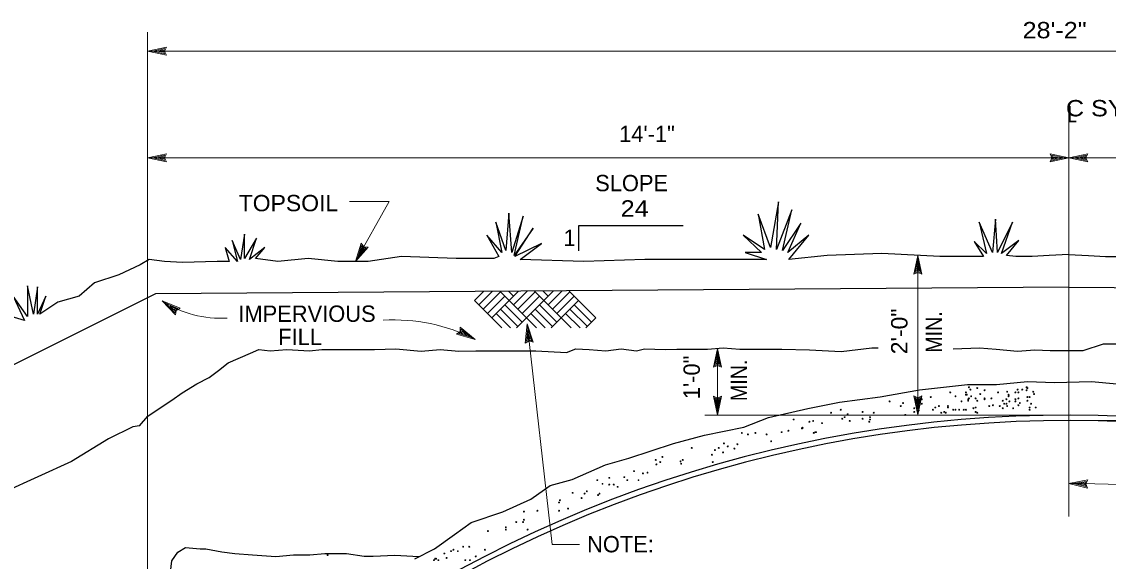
# Model space of a CAD drawing. Extents: x -24.3 to 17.7, y -17.6 to 12.4.
# Drawn here: x -17.91 to -9.61, y -5.14 to -1.01 of the extents above; entities that cross this region are included whole.
import ezdxf
from ezdxf.enums import TextEntityAlignment as Align

# ---------------------------------------------------------------- set-up
doc = ezdxf.new("R2010")
doc.units = 0
doc.header["$LTSCALE"] = 0.05
doc.layers.add('1', color=7, linetype='Continuous', lineweight=13)

msp = doc.modelspace()

# ---------------------------------------------------------------- linework, layer by layer
at = {"layer": '1'}
for p, q in [((-16.95069, -7.6306), (-16.95069, -1.0886)), ((-16.95069, -1.2326), (-16.80669, -1.2016)), ((-16.95069, -1.2326), (-2.86269, -1.2326)), ((-16.95069, -1.2326), (-16.80669, -1.2636)), ((-16.91369, -1.2326), (-16.81969, -1.2126)), ((-16.91369, -1.2326), (-16.81969, -1.2526)), ((-16.87769, -1.2326), (-16.83269, -1.2226)), ((-16.87769, -1.2326), (-16.83269, -1.2416)), ((-16.83269, -1.2226), (-16.83669, -1.2326)), ((-16.83669, -1.2326), (-16.83269, -1.2416)), ((-16.81969, -1.2126), (-16.82869, -1.2326)), ((-16.82869, -1.2326), (-16.81969, -1.2526)), ((-9.90869, -4.7916), (-9.90869, -1.6566)), ((-16.95069, -2.0496), (-16.80669, -2.0186)), ((-16.95069, -2.0496), (-16.80669, -2.0806)), ((-16.91369, -2.0496), (-16.81969, -2.0296)), ((-16.91369, -2.0496), (-16.81969, -2.0696)), ((-16.87769, -2.0496), (-16.83269, -2.0396)), ((-16.87769, -2.0496), (-16.83269, -2.0586)), ((-16.83269, -2.0396), (-16.83669, -2.0496)), ((-16.83669, -2.0496), (-16.83269, -2.0586)), ((-16.81969, -2.0296), (-16.82869, -2.0496)), ((-16.82869, -2.0496), (-16.81969, -2.0696)), ((-9.90769, -2.0496), (-10.05169, -2.0186)), ((-9.90769, -2.0496), (-10.05169, -2.0806)), ((-9.94469, -2.0496), (-10.03869, -2.0296)), ((-10.02969, -2.0496), (-10.03869, -2.0296)), ((-9.94469, -2.0496), (-10.03869, -2.0696)), ((-10.03869, -2.0696), (-10.02969, -2.0496)), ((-9.98069, -2.0496), (-10.02569, -2.0406)), ((-10.02169, -2.0496), (-10.02569, -2.0406)), ((-9.98069, -2.0496), (-10.02569, -2.0596)), ((-10.02569, -2.0596), (-10.02169, -2.0496)), ((-9.90769, -2.0496), (-9.76369, -2.0186)), ((-9.90769, -2.0496), (-9.76369, -2.0806)), ((-9.87069, -2.0496), (-9.77669, -2.0296)), ((-9.87069, -2.0496), (-9.77669, -2.0696)), ((-9.83469, -2.0496), (-9.78969, -2.0396)), ((-9.83469, -2.0496), (-9.78969, -2.0586)), ((-9.78969, -2.0396), (-9.79369, -2.0496)), ((-9.79369, -2.0496), (-9.78969, -2.0586)), ((-9.77669, -2.0296), (-9.78569, -2.0496)), ((-9.78569, -2.0496), (-9.77669, -2.0696)), ((-15.36169, -2.8426), (-15.26369, -2.7326)), ((-15.34369, -2.8106), (-15.31469, -2.7186)), ((-15.34369, -2.8106), (-15.27969, -2.7386)), ((-15.32569, -2.7786), (-15.31269, -2.7346)), ((-15.31469, -2.7186), (-15.30169, -2.7366)), ((-15.31269, -2.7346), (-15.30569, -2.7436)), ((-15.30169, -2.7366), (-15.27969, -2.7386)), ((-15.32569, -2.7786), (-15.29569, -2.7446)), ((-15.30569, -2.7436), (-15.29569, -2.7446)), ((-11.06169, -2.7956), (-11.09269, -2.9396)), ((-11.06169, -4.0166), (-11.06169, -2.7956)), ((-11.06169, -2.7956), (-11.03069, -2.9396)), ((-11.06169, -2.8326), (-11.08169, -2.9266)), ((-11.06169, -2.8686), (-11.07069, -2.9136)), ((-11.06169, -2.8326), (-11.04169, -2.9266)), ((-11.06169, -2.8686), (-11.05169, -2.9136)), ((-11.06169, -2.9176), (-11.08169, -2.9266)), ((-11.06169, -2.9096), (-11.07069, -2.9136)), ((-11.05169, -2.9136), (-11.06169, -2.9096)), ((-11.04169, -2.9266), (-11.06169, -2.9176)), ((-14.45069, -3.1406), (-14.37969, -3.0696)), ((-14.41769, -3.1736), (-14.31369, -3.0696)), ((-14.18569, -3.1406), (-14.25669, -3.0696)), ((-14.15269, -3.1076), (-14.19069, -3.0696)), ((-14.18569, -3.1406), (-14.11469, -3.0696)), ((-14.18569, -3.1406), (-14.11469, -3.0696)), ((-14.15269, -3.1736), (-14.04869, -3.0696)), ((-14.11969, -3.0746), (-14.12469, -3.0696)), ((-13.92069, -3.1406), (-13.99169, -3.0696)), ((-13.88769, -3.1076), (-13.92569, -3.0696)), ((-13.92069, -3.1406), (-13.84969, -3.0696)), ((-13.88769, -3.1736), (-13.78269, -3.0696)), ((-13.85469, -3.0746), (-13.85869, -3.0696)), ((-13.65569, -3.1406), (-13.72669, -3.0696)), ((-16.83769, -3.1426), (-16.70169, -3.1996)), ((-16.83769, -3.1426), (-16.73769, -3.2506)), ((-14.38469, -3.2066), (-14.25169, -3.0746)), ((-14.35169, -3.2406), (-14.21869, -3.1076)), ((-14.31869, -3.2736), (-14.18569, -3.1406)), ((-14.05269, -3.2736), (-14.18569, -3.1406)), ((-14.11969, -3.2066), (-13.98669, -3.0746)), ((-14.08669, -3.2406), (-13.95369, -3.1076)), ((-14.05269, -3.2736), (-13.92069, -3.1406)), ((-13.85469, -3.2066), (-13.72169, -3.0746)), ((-13.82069, -3.2406), (-13.68869, -3.1076)), ((-13.78769, -3.2736), (-13.65569, -3.1406)), ((-13.52269, -3.2736), (-13.65569, -3.1406)), ((-16.80769, -3.1636), (-16.71869, -3.2016)), ((-16.80769, -3.1636), (-16.74169, -3.2346)), ((-16.77769, -3.1846), (-16.74569, -3.2176)), ((-16.77769, -3.1846), (-16.73569, -3.2016)), ((-16.74469, -3.2076), (-16.74569, -3.2176)), ((-16.73569, -3.2016), (-16.74469, -3.2076)), ((-16.73769, -3.2126), (-16.74169, -3.2346)), ((-16.71869, -3.2016), (-16.73769, -3.2126)), ((-14.11969, -3.3396), (-14.25169, -3.2066)), ((-14.08669, -3.3066), (-14.21869, -3.1736)), ((-13.85469, -3.3396), (-13.98669, -3.2066)), ((-13.82069, -3.3066), (-13.95369, -3.1736)), ((-13.58869, -3.3396), (-13.72169, -3.2066)), ((-13.55569, -3.3066), (-13.68869, -3.1736)), ((-14.17569, -3.3496), (-14.28569, -3.2406)), ((-14.12969, -3.3496), (-14.05269, -3.2736)), ((-14.04869, -3.3196), (-14.06369, -3.4666)), ((-13.97669, -3.3496), (-14.05269, -3.2736)), ((-13.91069, -3.3496), (-14.01969, -3.2406)), ((-13.86469, -3.3496), (-13.78769, -3.2736)), ((-13.64469, -3.3496), (-13.75469, -3.2406)), ((-13.59969, -3.3496), (-13.52269, -3.2736)), ((-14.44669, -3.4376), (-14.58869, -3.3976)), ((-14.57169, -3.3946), (-14.55469, -3.3806)), ((-14.47969, -3.4206), (-14.57169, -3.3946)), ((-14.44669, -3.4376), (-14.55969, -3.3436)), ((-14.55569, -3.3916), (-14.54769, -3.3846)), ((-14.51169, -3.4036), (-14.55569, -3.3916)), ((-14.55469, -3.3806), (-14.55369, -3.3586)), ((-14.47969, -3.4206), (-14.55369, -3.3586)), ((-14.54769, -3.3846), (-14.54669, -3.3746)), ((-14.51169, -3.4036), (-14.54669, -3.3746)), ((-14.04469, -3.3566), (-14.05369, -3.4516)), ((-14.04469, -3.3566), (-14.01369, -3.4476)), ((-14.04069, -3.3926), (-14.04469, -3.4376)), ((-14.04069, -3.3926), (-14.02569, -3.4356)), ((-14.03469, -3.4406), (-14.05369, -3.4516)), ((-14.03569, -3.4326), (-14.04469, -3.4376)), ((-14.02569, -3.4356), (-14.03569, -3.4326)), ((-14.01369, -3.4476), (-14.03469, -3.4406)), ((-12.59369, -3.5066), (-12.62469, -3.6506)), ((-12.59369, -3.5436), (-12.61369, -3.6376)), ((-12.59369, -4.0166), (-12.59369, -3.5066)), ((-12.59369, -3.5066), (-12.56269, -3.6506)), ((-12.59369, -3.5436), (-12.57369, -3.6376)), ((-12.59369, -3.6286), (-12.61369, -3.6376)), ((-12.59369, -3.5796), (-12.60269, -3.6246)), ((-12.59369, -3.6206), (-12.60269, -3.6246)), ((-12.59369, -3.5796), (-12.58369, -3.6246)), ((-12.58369, -3.6246), (-12.59369, -3.6206)), ((-12.57369, -3.6376), (-12.59369, -3.6286)), ((-12.59369, -4.0166), (-12.62469, -3.8726)), ((-12.59369, -3.9796), (-12.61369, -3.8856)), ((-12.61369, -3.8856), (-12.59369, -3.8946)), ((-12.59369, -3.9436), (-12.60369, -3.8986)), ((-12.60369, -3.8986), (-12.59369, -3.9026)), ((-12.59369, -4.0166), (-12.56269, -3.8726)), ((-12.59369, -3.9796), (-12.57369, -3.8856)), ((-12.59369, -3.8946), (-12.57369, -3.8856)), ((-12.59369, -3.9436), (-12.58469, -3.8986)), ((-12.59369, -3.9026), (-12.58469, -3.8986)), ((-11.06169, -4.0136), (-11.09269, -3.8696)), ((-11.06169, -3.9766), (-11.08169, -3.8826)), ((-11.08169, -3.8826), (-11.06169, -3.8916)), ((-11.06169, -3.9406), (-11.07169, -3.8956)), ((-11.07169, -3.8956), (-11.06169, -3.8996)), ((-11.06169, -4.0136), (-11.03069, -3.8696)), ((-11.06169, -3.9766), (-11.04169, -3.8826)), ((-11.06169, -3.8916), (-11.04169, -3.8826)), ((-11.06169, -3.9406), (-11.05269, -3.8956)), ((-11.06169, -3.8996), (-11.05269, -3.8956)), ((-9.90269, -4.0166), (-12.69069, -4.0166)), ((-9.89169, -4.0586), (-9.94069, -4.0586)), ((-9.90969, -4.0576), (-0.82769, -4.0576)), ((-9.90869, -4.5396), (-9.76369, -4.5126)), ((-9.90869, -4.5396), (-9.76569, -4.5746)), ((-9.87169, -4.5406), (-9.77669, -4.5236)), ((-9.87169, -4.5406), (-9.77869, -4.5636)), ((-9.83569, -4.5416), (-9.79069, -4.5336)), ((-9.83569, -4.5416), (-9.79069, -4.5526)), ((-9.79069, -4.5336), (-9.79469, -4.5436)), ((-9.79469, -4.5436), (-9.79069, -4.5526)), ((-9.77669, -4.5236), (-9.78669, -4.5436)), ((-9.78669, -4.5436), (-9.77869, -4.5636)), ((-13.85769, -5.0076), (-13.64969, -5.0076))]:
    msp.add_line(p, q, dxfattribs=at)
at = {"layer": '1', "lineweight": 25}
for p, q in [((-9.90769, -3.0386), (-16.88969, -3.0886)), ((-16.88969, -3.0886), (-20.42169, -4.8536)), ((-17.01169, -4.0986), (-17.06169, -4.1056))]:
    msp.add_line(p, q, dxfattribs=at)
at = {"layer": '1'}
for points in [[(-16.80669, -1.2016), (-16.82069, -1.2326), (-16.80669, -1.2636)], [(-16.95069, -2.0496), (-9.90769, -2.0496), (-2.86269, -2.0496)], [(-16.80669, -2.0186), (-16.82069, -2.0496), (-16.80669, -2.0806)], [(-10.05169, -2.0806), (-10.03769, -2.0496), (-10.05169, -2.0186)], [(-9.76369, -2.0186), (-9.77769, -2.0496), (-9.76369, -2.0806)], [(-15.40669, -2.3826), (-15.10269, -2.3826), (-15.36169, -2.8426), (-15.31769, -2.7016)], [(-15.31769, -2.7016), (-15.29769, -2.7296), (-15.26369, -2.7326)], [(-11.03069, -2.9396), (-11.06169, -2.9256), (-11.09269, -2.9396)], [(-13.71169, -3.3496), (-13.92069, -3.1406), (-13.84969, -3.0696)], [(-14.24169, -3.3496), (-14.31869, -3.2736), (-14.45069, -3.1406)], [(-16.70169, -3.1996), (-16.73069, -3.2176), (-16.73769, -3.2506)], [(-13.85769, -5.0076), (-14.04869, -3.3196), (-14.00169, -3.4596)], [(-14.58869, -3.3976), (-14.56169, -3.3766), (-14.55969, -3.3436)], [(-14.00169, -3.4596), (-14.03369, -3.4486), (-14.06369, -3.4666)], [(-12.56269, -3.6506), (-12.59369, -3.6366), (-12.62469, -3.6506)], [(-12.62469, -3.8726), (-12.59369, -3.8866), (-12.56269, -3.8726)], [(-11.09269, -3.8696), (-11.06169, -3.8836), (-11.03069, -3.8696)], [(-9.76369, -4.5126), (-9.77869, -4.5436), (-9.76569, -4.5746)]]:
    msp.add_lwpolyline(points, dxfattribs=at)
at = {"layer": '1', "lineweight": 25}
for points in [[(-9.90769, -2.7886), (-10.05869, -2.7966), (-10.18969, -2.8046), (-10.31369, -2.8046), (-10.38369, -2.7966), (-10.29069, -2.6806), (-10.42269, -2.7816), (-10.33769, -2.5406), (-10.45369, -2.7736), (-10.46869, -2.5176), (-10.49269, -2.7736), (-10.59269, -2.5406), (-10.53869, -2.7816), (-10.63169, -2.6886), (-10.56169, -2.8046), (-10.89469, -2.8046), (-11.33669, -2.7816), (-11.75469, -2.7966), (-12.04969, -2.8276), (-11.89469, -2.6416), (-12.05669, -2.7736), (-11.95669, -2.5486), (-12.09569, -2.7576), (-12.02669, -2.4476), (-12.14269, -2.7506), (-12.12669, -2.3856), (-12.18869, -2.7346), (-12.28169, -2.4786), (-12.23569, -2.7506), (-12.39769, -2.6416), (-12.25869, -2.7736), (-12.38269, -2.7736), (-12.21969, -2.8276), (-12.79269, -2.8276), (-13.14969, -2.8276), (-13.61469, -2.8426), (-14.10269, -2.8276), (-13.93969, -2.7036), (-14.14169, -2.8046), (-14.00169, -2.5876), (-14.14869, -2.7966), (-14.07969, -2.4946), (-14.16469, -2.7736), (-14.18769, -2.4716), (-14.21069, -2.7576), (-14.28869, -2.5406), (-14.24169, -2.7736), (-14.35769, -2.6416), (-14.26569, -2.8046), (-14.30369, -2.8196), (-14.59069, -2.8196), (-15.00869, -2.8046), (-15.26469, -2.8426), (-15.49669, -2.8426), (-15.72169, -2.8196), (-15.95369, -2.8426), (-16.12469, -2.8196), (-16.05469, -2.7346), (-16.17069, -2.8276), (-16.11669, -2.6646), (-16.20969, -2.8196), (-16.20969, -2.6336), (-16.24069, -2.8276), (-16.30269, -2.6806), (-16.26369, -2.8426), (-16.35669, -2.7346), (-16.32569, -2.8426), (-16.41869, -2.8426), (-16.68269, -2.8506), (-16.82169, -2.8426), (-16.93769, -2.8276), (-17.00769, -2.8666), (-17.17069, -2.9436), (-17.35669, -3.0056), (-17.47269, -3.1066), (-17.63569, -3.1526), (-17.77469, -3.2456), (-17.72869, -3.1066), (-17.79069, -3.2456), (-17.79069, -3.0366), (-17.82169, -3.2456), (-17.86769, -3.0286), (-17.86769, -3.2616), (-17.97669, -3.1066), (-17.89069, -3.2926), (-18.06969, -3.2386)], [(-13.65469, -2.7616), (-13.65469, -2.5666), (-12.85669, -2.5666)], [(-9.90969, -2.7886), (-9.75869, -2.7966), (-9.62769, -2.8046), (-9.50369, -2.8046)], [(-9.91169, -3.0386), (-2.92769, -3.0886), (0.66231, -4.8826)], [(-10.16769, -3.5166), (-10.05169, -3.5216), (-9.79869, -3.5216), (-9.64269, -3.4726), (-9.24269, -3.4726), (-8.95069, -3.4726)], [(-17.01169, -4.0986), (-16.94869, -4.0256), (-16.87569, -3.9766), (-16.76369, -3.9036), (-16.68569, -3.8456), (-16.57369, -3.7776), (-16.48069, -3.7286), (-16.40769, -3.6756), (-16.33469, -3.6166), (-16.16469, -3.5436), (-16.10069, -3.5146), (-16.01369, -3.5246), (-15.88669, -3.5146), (-15.71169, -3.5246), (-15.61869, -3.5146), (-15.37069, -3.5146), (-15.21469, -3.5146), (-15.05369, -3.5096), (-14.85969, -3.5286), (-14.71369, -3.5146), (-14.57169, -3.5286), (-14.44069, -3.5246), (-14.26569, -3.5246), (-14.14369, -3.5246), (-13.98269, -3.5246), (-13.74869, -3.5386), (-13.67569, -3.5096), (-13.57369, -3.5146), (-13.44769, -3.5246), (-13.33069, -3.5096), (-13.21369, -3.5246), (-13.15069, -3.5096), (-12.99469, -3.5146)], [(-12.99469, -3.5146), (-12.90469, -3.5116), (-12.78269, -3.5116), (-12.67069, -3.5116), (-12.54969, -3.5016), (-12.42269, -3.5116), (-12.25669, -3.5116), (-12.10169, -3.5116), (-11.89169, -3.5166), (-11.64869, -3.5316), (-11.41469, -3.5016), (-11.36569, -3.5016)], [(-10.79169, -3.5096), (-10.59169, -3.5016), (-10.46469, -3.5116), (-10.29969, -3.5266), (-10.16769, -3.5166)], [(-14.90769, -5.1156), (-14.75669, -5.0396), (-14.60369, -4.9296), (-14.47769, -4.8396), (-14.23469, -4.7556), (-14.01969, -4.6606), (-13.87169, -4.5556), (-13.70369, -4.5086), (-13.45069, -4.3976), (-13.27169, -4.3456), (-12.92969, -4.2346), (-12.69269, -4.1716), (-12.39269, -4.1086), (-12.20369, -4.0346), (-11.90369, -3.9666), (-11.66169, -3.9186), (-11.35069, -3.8766), (-11.05069, -3.8246), (-10.68269, -3.7816), (-10.46169, -3.7816), (-10.22469, -3.7606), (-10.01869, -3.7666), (-9.73469, -3.7606), (-9.37669, -3.7926)], [(-17.06169, -4.1056), (-17.24969, -4.1996), (-17.53069, -4.3716), (-18.04769, -4.6066), (-18.50069, -4.8406), (-19.07969, -5.1696), (-19.48569, -5.3726), (-19.87669, -5.5606), (-20.15869, -5.6856)], [(-16.77569, -5.2186), (-16.76469, -5.1326), (-16.71969, -5.0656), (-16.66069, -5.0286), (-16.54769, -5.0396), (-16.50369, -5.0396), (-16.38369, -5.0616), (-16.28269, -5.0766), (-16.14769, -5.0846), (-15.96869, -5.0996), (-15.83369, -5.0846), (-15.71069, -5.0846), (-15.59469, -5.0766), (-15.43069, -5.0766), (-15.29569, -5.0956), (-15.22469, -5.0956), (-15.05969, -5.0876), (-14.87669, -5.0996)]]:
    msp.add_lwpolyline(points, dxfattribs=at)
at = {"layer": '1'}
for centre in [(-10.67169, -3.8036), (-10.66069, -3.8216), (-10.60869, -3.8096), (-10.29969, -3.8216), (-10.26469, -3.8216), (-10.23069, -3.8036), (-10.22469, -3.8096), (-11.03269, -3.8956), (-10.96369, -3.8786), (-10.81469, -3.8436), (-10.77469, -3.8726), (-10.69469, -3.8436), (-10.69469, -3.8616), (-10.68869, -3.8616), (-10.67769, -3.8956), (-10.67769, -3.9066), (-10.67169, -3.8896), (-10.65469, -3.8726), (-10.62069, -3.8896), (-10.60869, -3.9066), (-10.58569, -3.8556), (-10.55169, -3.8266), (-10.55169, -3.8896), (-10.55169, -3.8956), (-10.49969, -3.8896), (-10.44869, -3.8436), (-10.41369, -3.9066), (-10.38569, -3.8956), (-10.37969, -3.8386), (-10.36869, -3.8616), (-10.36869, -3.8726), (-10.31669, -3.8436), (-10.31669, -3.8956), (-10.29369, -3.8436), (-10.29369, -3.8896), (-10.23069, -3.8266), (-10.22469, -3.8786), (-10.22469, -3.9066), (-10.20769, -3.8786), (-10.17969, -3.8386), (-10.17369, -3.8556), (-11.65169, -3.9756), (-11.27869, -3.9126), (-11.19269, -3.9476), (-11.17569, -3.9246), (-11.08969, -3.9646), (-11.05569, -3.9816), (-11.03269, -3.9296), (-10.94669, -3.9756), (-10.92969, -3.9586), (-10.90069, -3.9476), (-10.83269, -3.9476), (-10.83269, -3.9586), (-10.79169, -3.9756), (-10.77469, -3.9756), (-10.74669, -3.9756), (-10.72869, -3.9126), (-10.71169, -3.9756), (-10.69469, -3.9756), (-10.63769, -3.9646), (-10.62069, -3.9586), (-10.51669, -3.9476), (-10.48869, -3.9416), (-10.48869, -3.9416), (-10.43669, -3.9476), (-10.41369, -3.9646), (-10.40269, -3.9296), (-10.38569, -3.9296), (-10.37969, -3.9476), (-10.36269, -3.9126), (-10.33369, -3.9646), (-10.31669, -3.9126), (-10.29369, -3.9416), (-10.28269, -3.9246), (-10.20769, -3.9586), (-10.20769, -3.9756), (-10.19669, -3.9296), (-10.16169, -3.9586), (-12.01169, -4.0506), (-11.89169, -4.0676), (-11.86269, -4.0616), (-11.72569, -3.9986), (-11.63969, -4.0446), (-11.62269, -4.0326), (-11.59969, -4.0106), (-11.58269, -4.0616), (-11.48469, -3.9926), (-11.48469, -4.0446), (-11.43369, -4.0676), (-11.42769, -4.0326), (-11.42769, -4.0506), (-11.39969, -3.9986), (-11.15869, -4.0156), (-11.08969, -3.9926), (-10.88369, -3.9986), (-10.86069, -3.9926), (-10.84969, -3.9986), (-10.62069, -3.9926), (-10.60869, -3.9986), (-12.40769, -4.1536), (-12.30369, -4.1536), (-12.10369, -4.1476), (-12.05169, -4.1366), (-11.94869, -4.1186), (-11.94369, -4.1136), (-11.85769, -4.1536), (-11.84569, -4.1476), (-11.84069, -4.1476), (-11.79469, -4.0786), (-12.54469, -4.2336), (-12.36169, -4.1646), (-12.21869, -4.1646), (-12.18369, -4.2166), (-12.79069, -4.2676), (-12.63669, -4.3196), (-12.61369, -4.2846), (-12.58469, -4.2676), (-12.55069, -4.3026), (-12.51569, -4.2566), (-12.46469, -4.2736), (-12.44169, -4.2396), (-13.06569, -4.3596), (-13.06069, -4.3936), (-13.03169, -4.3766), (-13.01469, -4.3366), (-12.87669, -4.3706), (-12.87169, -4.3886), (-12.85969, -4.3596), (-12.63069, -4.3766), (-13.23169, -4.4456), (-13.16369, -4.4626), (-13.12869, -4.4566), (-13.51269, -4.5146), (-13.47269, -4.5426), (-13.42069, -4.4966), (-13.42069, -4.5486), (-13.38669, -4.5486), (-13.35769, -4.5656), (-13.30669, -4.4916), (-13.28369, -4.5146), (-13.19769, -4.5146), (-13.70169, -4.6116), (-13.63269, -4.6516), (-13.60969, -4.6176), (-13.59269, -4.5996), (-13.50669, -4.6286), (-13.49569, -4.6176), (-13.80469, -4.6856), (-13.79869, -4.6686), (-13.73569, -4.7316), (-14.07369, -4.7546), (-14.07369, -4.8176), (-13.97069, -4.7486), (-13.80469, -4.7486), (-14.34869, -4.9036), (-14.34869, -4.9036), (-14.21169, -4.8746), (-14.21169, -4.8926), (-14.13169, -4.8346), (-14.07969, -4.8346), (-14.04569, -4.8926), (-14.63069, -5.0576), (-14.61269, -5.0466), (-14.57869, -5.0576), (-14.53769, -5.0236), (-14.49169, -5.0236), (-14.37169, -5.0466), (-15.57369, -5.0876), (-14.76169, -5.1266), (-14.75069, -5.1156), (-14.74469, -5.1156), (-14.72769, -5.1266), (-14.68169, -5.0756), (-14.66469, -5.1096), (-14.52169, -5.1266), (-14.48669, -5.1266), (-14.44169, -5.0976)]:
    msp.add_circle(centre, 0.00361, dxfattribs=at)
for centre, radius, start, end in [((-16.39109, -2.46275), 0.81341, 236.69915, 273.55285), ((-15.06162, -4.63364), 1.34486, 62.79052, 93.71202), ((-9.90869, -13.7666), 9.22657, 50.60311, 90)]:
    msp.add_arc(centre, radius, start, end, dxfattribs=at)
at = {"layer": '1', "lineweight": 25}
for radius in [9.74984, 9.70818]:
    msp.add_arc((-9.90906, -13.7666), radius, 49.71979, 130.09764, dxfattribs=at)

# ---------------------------------------------------------------- texts
at = {"layer": '1'}
for s, width, p in [('28\'-2"', 1.15, (-10.26169, -1.1346)), ('C SYMM.', 1.15, (-9.93069, -1.7316)), ('L', 0.75, (-9.91569, -1.7776)), ('TOPSOIL', 1.05, (-16.25369, -2.4576)), ('24', 1.15, (-13.33369, -2.4986))]:
    msp.add_text(s, height=0.125, dxfattribs=dict(at, width=width)).set_placement(p)
for s, p in [('14\'-1"', (-13.13269, -1.9286)), ('SLOPE', (-13.25019, -2.3046)), ('IMPERVIOUS', (-15.73169, -3.3036)), ('FILL', (-15.78419, -3.4816))]:
    msp.add_text(s, height=0.125, dxfattribs=at).set_placement(p, align=Align.CENTER)
for s, p in [('1', (-13.77169, -2.7236)), ('NOTE:', (-13.59069, -5.0666))]:
    msp.add_text(s, height=0.125, dxfattribs=at).set_placement(p)
for s, width, p in [('2\'-0"', 1.05, (-11.14169, -3.3766)), ('MIN.', 0.9, (-10.87769, -3.3811)), ('MIN.', 0.9, (-12.36769, -3.7511))]:
    msp.add_text(s, height=0.125, rotation=90, dxfattribs=dict(at, width=width)).set_placement(p, align=Align.CENTER)
msp.add_text('1\'-0"', height=0.125, rotation=90, dxfattribs=at).set_placement((-12.72869, -3.7286), align=Align.CENTER)

doc.saveas('drawing.dxf')
